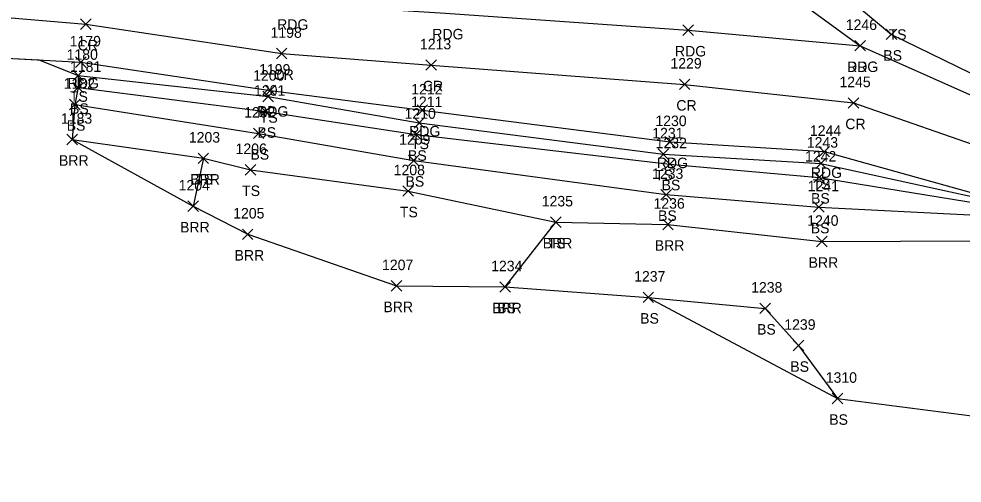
# Model space of a CAD drawing. Extents: x 1600281 to 1602254, y 862855 to 863227.
# Drawn here: x 1601747.6 to 1601927.2, y 862860.3 to 862948.7 of the extents above; entities that cross this region are included whole.
import ezdxf

# ---------------------------------------------------------------- set-up
doc = ezdxf.new("R2010")
doc.units = 0
for name, color, linetype in [('L_A', 7, 'Continuous'), ('L_I', 7, 'Continuous'), ('L_TIC', 7, 'Continuous'), ('LABL', 7, 'Continuous'), ('LELB', 7, 'Continuous'), ('LSOGP', 7, 'Continuous'), ('P_A', 7, 'Continuous'), ('P_I', 7, 'Continuous'), ('P_TIC', 7, 'Continuous'), ('PEU', 7, 'Continuous'), ('PRC', 7, 'Continuous'), ('R_A', 7, 'Continuous'), ('R_I', 7, 'Continuous'), ('R_TIC', 7, 'Continuous'), ('RDG', 7, 'Continuous')]:
    doc.layers.add(name, color=color, linetype=linetype)

msp = doc.modelspace()

# ---------------------------------------------------------------- linework, layer by layer
at = {"layer": 'L_TIC'}
for points in [[(1601912.79, 862944.71), (1601914.79, 862946.71)], [(1601914.79, 862944.71), (1601912.79, 862946.71)], [(1601757.89, 862936.88), (1601759.89, 862938.88)], [(1601759.89, 862936.88), (1601757.89, 862938.88)], [(1601757.87, 862934.58), (1601759.87, 862936.58)], [(1601759.87, 862934.58), (1601757.87, 862936.58)], [(1601794.07, 862932.9), (1601796.07, 862934.9)], [(1601796.07, 862932.9), (1601794.07, 862934.9)], [(1601757.25, 862931.38), (1601759.25, 862933.38)], [(1601759.25, 862931.38), (1601757.25, 862933.38)], [(1601793.57, 862930.04), (1601795.57, 862932.04)], [(1601795.57, 862930.04), (1601793.57, 862932.04)], [(1601822.85, 862927.87), (1601824.85, 862929.87)], [(1601824.85, 862927.87), (1601822.85, 862929.87)], [(1601792.25, 862925.87), (1601794.25, 862927.87)], [(1601794.25, 862925.87), (1601792.25, 862927.87)], [(1601822.26, 862925.65), (1601824.26, 862927.65)], [(1601824.26, 862925.65), (1601822.26, 862927.65)], [(1601756.73, 862924.71), (1601758.73, 862926.71)], [(1601758.73, 862924.71), (1601756.73, 862926.71)], [(1601869.34, 862921.92), (1601871.34, 862923.92)], [(1601871.34, 862921.92), (1601869.34, 862923.92)], [(1601781.73, 862921.12), (1601783.73, 862923.12)], [(1601783.73, 862921.12), (1601781.73, 862923.12)], [(1601781.73, 862921.12), (1601783.73, 862923.12)], [(1601783.73, 862921.12), (1601781.73, 862923.12)], [(1601821.78, 862920.72), (1601823.78, 862922.72)], [(1601823.78, 862920.72), (1601821.78, 862922.72)], [(1601870.56, 862920.03), (1601872.56, 862922.03)], [(1601872.56, 862920.03), (1601870.56, 862922.03)], [(1601899.35, 862920.15), (1601901.35, 862922.15)], [(1601901.35, 862920.15), (1601899.35, 862922.15)], [(1601790.69, 862918.94), (1601792.69, 862920.94)], [(1601792.69, 862918.94), (1601790.69, 862920.94)], [(1601899.01, 862917.49), (1601901.01, 862919.49)], [(1601901.01, 862917.49), (1601899.01, 862919.49)], [(1601820.74, 862914.89), (1601822.74, 862916.89)], [(1601822.74, 862914.89), (1601820.74, 862916.89)], [(1601869.88, 862914.2), (1601871.88, 862916.2)], [(1601871.88, 862914.2), (1601869.88, 862916.2)], [(1601779.79, 862912), (1601781.79, 862914)], [(1601781.79, 862912), (1601779.79, 862914)], [(1601898.96, 862911.84), (1601900.96, 862913.84)], [(1601900.96, 862911.84), (1601898.96, 862913.84)], [(1601848.86, 862908.96), (1601850.86, 862910.96)], [(1601850.86, 862908.96), (1601848.86, 862910.96)], [(1601848.86, 862908.96), (1601850.86, 862910.96)], [(1601850.86, 862908.96), (1601848.86, 862910.96)], [(1601870.21, 862908.53), (1601872.21, 862910.53)], [(1601872.21, 862908.53), (1601870.21, 862910.53)], [(1601790.17, 862906.66), (1601792.17, 862908.66)], [(1601792.17, 862906.66), (1601790.17, 862908.66)], [(1601899.52, 862905.28), (1601901.52, 862907.28)], [(1601901.52, 862905.28), (1601899.52, 862907.28)], [(1601818.52, 862896.83), (1601820.52, 862898.83)], [(1601820.52, 862896.83), (1601818.52, 862898.83)], [(1601839.22, 862896.63), (1601841.22, 862898.63)], [(1601841.22, 862896.63), (1601839.22, 862898.63)], [(1601839.22, 862896.63), (1601841.22, 862898.63)], [(1601841.22, 862896.63), (1601839.22, 862898.63)], [(1601866.46, 862894.65), (1601868.46, 862896.65)], [(1601868.46, 862894.65), (1601866.46, 862896.65)], [(1601888.74, 862892.56), (1601890.74, 862894.56)], [(1601890.74, 862892.56), (1601888.74, 862894.56)], [(1601895.07, 862885.48), (1601897.07, 862887.48)], [(1601897.07, 862885.48), (1601895.07, 862887.48)], [(1601902.49, 862875.39), (1601904.49, 862877.39)], [(1601904.49, 862875.39), (1601902.49, 862877.39)]]:
    msp.add_lwpolyline(points, dxfattribs=at)
at = {"layer": 'LABL'}
msp.add_lwpolyline([(1601757.73, 862925.71), (1601782.73, 862922.12), (1601780.79, 862913), (1601791.17, 862907.66), (1601819.52, 862897.83), (1601840.22, 862897.63), (1601849.86, 862909.96), (1601871.21, 862909.53), (1601900.52, 862906.28), (1601930.51, 862906.39), (1601953.03, 862897.22), (1601970.52, 862894.75), (1601991.9, 862890.49), (1601990.89, 862878.43), (1601986.33, 862860.29)], dxfattribs=at)
at = {"layer": 'LELB'}
for points in [[(1601850.49, 862982.97), (1601860.82, 862978.52), (1601879.36, 862968.78), (1601889.4, 862966.06), (1601913.79, 862945.71), (1601936.18, 862934.79), (1601959, 862928.54), (1601973.11, 862927.74), (1601983.04, 862929.48), (1601994.91, 862935.46), (1602008.18, 862945.23), (1602016.32, 862961.34), (1602018.76, 862980.32), (1602014.94, 863002.44), (1602007.85, 863017.62), (1602006.36, 863023.32), (1602003.16, 863037.99), (1602002.76, 863044.77), (1602006.6, 863051.13), (1602010.65, 863053.19)], [(1601758.25, 862932.38), (1601793.25, 862926.87), (1601822.78, 862921.72), (1601870.88, 862915.2), (1601899.96, 862912.84), (1601930, 862911.27), (1601955.11, 862904.27), (1601972.4, 862900.45), (1601993.87, 862895.1), (1602006.95, 862889.06), (1602013.67, 862890.43), (1602037.38, 862895.19), (1602041.45, 862902.14), (1602044.34, 862911.83), (1602073.39, 862917.1), (1602080.57, 862918.06), (1602084.27, 862928.9), (1602082.1, 862942.17), (1602076.79, 862963.57), (1602077.84, 862979.48), (1602084.81, 862995.17), (1602084.83, 863009.34), (1602087.06, 863019.48), (1602088.42, 863022.64)], [(1601758.87, 862935.58), (1601794.57, 862931.04), (1601823.26, 862926.65), (1601871.56, 862921.03), (1601900.01, 862918.49), (1601930.47, 862913.51), (1601956.16, 862906.35), (1601972.87, 862902.68), (1601993.62, 862897.85), (1602007.26, 862890.97), (1602013.99, 862891.89), (1602036.74, 862896.62), (1602039.12, 862902.94), (1602042.65, 862913.22), (1602071.45, 862922.17), (1602077.73, 862924.94), (1602083, 862929.53), (1602079.85, 862943.1), (1602074.85, 862964.04), (1602072.57, 862980.37), (1602075.41, 862992.31), (1602081.73, 863011.09), (1602084.93, 863020.57), (1602086.17, 863023.52)], [(1601758.89, 862937.88), (1601795.07, 862933.9), (1601823.85, 862928.87), (1601870.34, 862922.92), (1601900.35, 862921.15), (1601930.52, 862914.56), (1601956.2, 862907.26), (1601973.32, 862904.61), (1601993.85, 862900), (1602008.19, 862895.02), (1602014.42, 862895.34), (1602035.61, 862898.84), (1602036.45, 862903.94), (1602042.39, 862916.03), (1602070.54, 862924.32), (1602075.87, 862928.13), (1602081.56, 862930.04), (1602078.85, 862942.66), (1602073.58, 862963.52), (1602071.23, 862980.75), (1602072.26, 862993.36), (1602076.69, 863007.7), (1602078.09, 863013.39), (1602083.85, 863020.87)], [(1601782.73, 862922.12), (1601791.69, 862919.94), (1601821.74, 862915.89), (1601849.86, 862909.96)], [(1601840.22, 862897.63), (1601867.46, 862895.65), (1601889.74, 862893.56), (1601896.07, 862886.48), (1601903.49, 862876.39)]]:
    msp.add_lwpolyline(points, dxfattribs=at)
at = {"layer": 'LSOGP'}
msp.add_lwpolyline([(1601741.4, 862941.39), (1601751.39, 862940.85), (1601758.89, 862937.88), (1601758.87, 862935.58), (1601758.25, 862932.38), (1601757.73, 862925.71), (1601780.79, 862913), (1601791.17, 862907.66), (1601819.52, 862897.83), (1601840.22, 862897.63), (1601867.46, 862895.65), (1601903.49, 862876.39), (1601931.07, 862872.82)], dxfattribs=at)
at = {"layer": 'P_TIC'}
for points in [[(1601759.35, 862946.65), (1601761.35, 862948.65)], [(1601761.35, 862946.65), (1601759.35, 862948.65)], [(1601874.05, 862945.51), (1601876.05, 862947.51)], [(1601876.05, 862945.51), (1601874.05, 862947.51)], [(1601906.83, 862942.55), (1601908.83, 862944.55)], [(1601908.83, 862942.55), (1601906.83, 862944.55)], [(1601758.39, 862939.42), (1601760.39, 862941.42)], [(1601760.39, 862939.42), (1601758.39, 862941.42)], [(1601796.64, 862941.06), (1601798.64, 862943.06)], [(1601798.64, 862941.06), (1601796.64, 862943.06)], [(1601825.1, 862938.87), (1601827.1, 862940.87)], [(1601827.1, 862938.87), (1601825.1, 862940.87)], [(1601794.48, 862934.05), (1601796.48, 862936.05)], [(1601796.48, 862934.05), (1601794.48, 862936.05)], [(1601873.38, 862935.2), (1601875.38, 862937.2)], [(1601875.38, 862935.2), (1601873.38, 862937.2)], [(1601905.56, 862931.66), (1601907.56, 862933.66)], [(1601907.56, 862931.66), (1601905.56, 862933.66)], [(1601823.44, 862930.28), (1601825.44, 862932.28)], [(1601825.44, 862930.28), (1601823.44, 862932.28)], [(1601870.6, 862924.25), (1601872.6, 862926.25)], [(1601872.6, 862924.25), (1601870.6, 862926.25)], [(1601899.95, 862922.39), (1601901.95, 862924.39)], [(1601901.95, 862922.39), (1601899.95, 862924.39)]]:
    msp.add_lwpolyline(points, dxfattribs=at)
at = {"layer": 'PEU'}
for points in [[(1601721.43, 862942.48), (1601759.39, 862940.42), (1601795.48, 862935.05), (1601824.44, 862931.28), (1601871.6, 862925.25), (1601900.95, 862923.39), (1601930.54, 862915.16), (1601956.45, 862910.48), (1601973.53, 862907.72), (1601992.87, 862904.84), (1602011.43, 862910.06), (1602025.54, 862921.56), (1602034.6, 862951.41), (1602037.17, 862973.14), (1602036.63, 863000.37), (1602039.38, 863008.7), (1602041.94, 863026.81), (1602046.4, 863038.48), (1602048.21, 863041.76), (1602041.55, 863045.82), (1602034.19, 863049.73), (1602032.2, 863046.61)], [(1601722.64, 862959.62), (1601760.79, 862956.05), (1601799.29, 862951.59), (1601828.84, 862949.76), (1601875.05, 862946.51), (1601907.83, 862943.55), (1601935.49, 862931.23), (1601958.79, 862926.46), (1601973.44, 862925.27), (1601984.38, 862925.96), (1601999.67, 862930.14), (1602015.04, 862942.76), (1602018.56, 862960.18), (1602022.83, 862979.22), (1602021.22, 863002.76), (1602025.96, 863016.12), (1602028.23, 863030.49), (1602032.2, 863046.61)]]:
    msp.add_lwpolyline(points, dxfattribs=at)
at = {"layer": 'PRC'}
msp.add_lwpolyline([(1601722.03, 862950.92), (1601760.35, 862947.65), (1601797.64, 862942.06), (1601826.1, 862939.87), (1601874.38, 862936.2), (1601906.56, 862932.66), (1601933.52, 862923.27), (1601957.93, 862920.04), (1601974.08, 862916.23), (1601989.5, 862915.67), (1602005.13, 862920.56), (1602020.05, 862931.21), (1602025.88, 862956.8), (1602029.68, 862975.25), (1602029.18, 863001.63), (1602032.15, 863012.73), (1602036.07, 863028.12), (1602041.55, 863045.82)], dxfattribs=at)
at = {"layer": 'R_TIC'}
for points in [[(1601906.83, 862942.55), (1601908.83, 862944.55)], [(1601908.83, 862942.55), (1601906.83, 862944.55)]]:
    msp.add_lwpolyline(points, dxfattribs=at)
at = {"layer": 'RDG'}
msp.add_lwpolyline([(1601760.79, 862956.05), (1601782.18, 862967.72), (1601801.88, 862976.53), (1601832.63, 862976.97), (1601878.13, 862965.22), (1601907.83, 862943.55)], dxfattribs=at)

# ---------------------------------------------------------------- texts
at = {"layer": 'L_A'}
for s, p in [('TS', (1601913.23, 862944.68)), ('BS', (1601912.23, 862940.71)), ('TS', (1601757.3, 862932.88)), ('BS', (1601757.32, 862930.58)), ('TS', (1601793.48, 862928.9)), ('BS', (1601756.69, 862927.38)), ('BS', (1601793.01, 862926.04)), ('TS', (1601822.26, 862923.87)), ('BS', (1601791.69, 862921.87)), ('BS', (1601821.7, 862921.65)), ('BRR', (1601755.22, 862920.71)), ('TS', (1601868.75, 862917.92)), ('BRR', (1601780.22, 862917.12)), ('TS', (1601781.14, 862917.12)), ('BS', (1601821.22, 862916.72)), ('BS', (1601870, 862916.03)), ('TS', (1601898.76, 862916.15)), ('TS', (1601790.1, 862914.94)), ('BS', (1601898.46, 862913.49)), ('TS', (1601820.15, 862910.89)), ('BS', (1601869.32, 862910.2)), ('BRR', (1601778.28, 862908)), ('BS', (1601898.4, 862907.84)), ('BRR', (1601847.35, 862904.96)), ('TS', (1601848.27, 862904.96)), ('BRR', (1601868.69, 862904.53)), ('BRR', (1601788.66, 862902.66)), ('BRR', (1601898, 862901.28)), ('BRR', (1601817.01, 862892.83)), ('BRR', (1601837.71, 862892.63)), ('BS', (1601838.66, 862892.63)), ('BS', (1601865.91, 862890.65)), ('BS', (1601888.18, 862888.56)), ('BS', (1601894.51, 862881.48)), ('BS', (1601901.93, 862871.39))]:
    msp.add_text(s, height=2, dxfattribs=at).set_placement(p)
at = {"layer": 'L_I'}
for s, p in [('1180', (1601756.68, 862940.88)), ('1181', (1601757.32, 862938.58)), ('1200', (1601792.21, 862936.9)), ('1182', (1601756.13, 862935.38)), ('1201', (1601792.37, 862934.04)), ('1211', (1601822.29, 862931.87)), ('1183', (1601755.6, 862928.71)), ('1202', (1601790.48, 862929.87)), ('1210', (1601821.04, 862929.65)), ('1203', (1601779.96, 862925.12)), ('1203', (1601779.96, 862925.12)), ('1231', (1601868.22, 862925.92)), ('1209', (1601820, 862924.72)), ('1232', (1601868.87, 862924.03)), ('1243', (1601897.66, 862924.15)), ('1206', (1601788.86, 862922.94)), ('1242', (1601897.32, 862921.49)), ('1208', (1601818.97, 862918.89)), ('1233', (1601868.18, 862918.2)), ('1204', (1601778.02, 862916)), ('1241', (1601897.83, 862915.84)), ('1235', (1601847.17, 862912.96)), ('1235', (1601847.17, 862912.96)), ('1236', (1601868.46, 862912.53)), ('1205', (1601788.4, 862910.66)), ('1240', (1601897.74, 862909.28)), ('1207', (1601816.75, 862900.83)), ('1234', (1601837.53, 862900.63)), ('1234', (1601837.53, 862900.63)), ('1237', (1601864.77, 862898.65)), ('1238', (1601887.05, 862896.56)), ('1239', (1601893.37, 862889.48)), ('1310', (1601901.27, 862879.39))]:
    msp.add_text(s, height=2, dxfattribs=at).set_placement(p)
at = {"layer": 'P_A'}
for s, p in [('RDG', (1601796.78, 862946.59)), ('RDG', (1601826.33, 862944.76)), ('CR', (1601758.78, 862942.65)), ('RDG', (1601872.54, 862941.51)), ('RDG', (1601905.32, 862938.55)), ('CR', (1601796.08, 862937.06)), ('RDG', (1601756.88, 862935.42)), ('CR', (1601824.53, 862934.87)), ('CR', (1601872.81, 862931.2)), ('RDG', (1601792.96, 862930.05)), ('CR', (1601904.99, 862927.66)), ('RDG', (1601821.92, 862926.28)), ('RDG', (1601869.09, 862920.25)), ('RDG', (1601898.43, 862918.39))]:
    msp.add_text(s, height=2, dxfattribs=at).set_placement(p)
at = {"layer": 'P_I'}
for s, p in [('1246', (1601905.08, 862946.55)), ('1198', (1601795.52, 862945.06)), ('1179', (1601757.26, 862943.42)), ('1213', (1601823.97, 862942.87)), ('1199', (1601793.34, 862938.05)), ('1229', (1601871.68, 862939.2)), ('1212', (1601822.31, 862934.28)), ('1245', (1601903.87, 862935.66)), ('1230', (1601868.82, 862928.25)), ('1244', (1601898.25, 862926.39))]:
    msp.add_text(s, height=2, dxfattribs=at).set_placement(p)
at = {"layer": 'R_A'}
msp.add_text('DRG', height=2, dxfattribs=at).set_placement((1601905.32, 862938.55))
at = {"layer": 'R_I'}
msp.add_text('1246', height=2, dxfattribs=at).set_placement((1601905.08, 862946.55))

doc.saveas('drawing.dxf')
